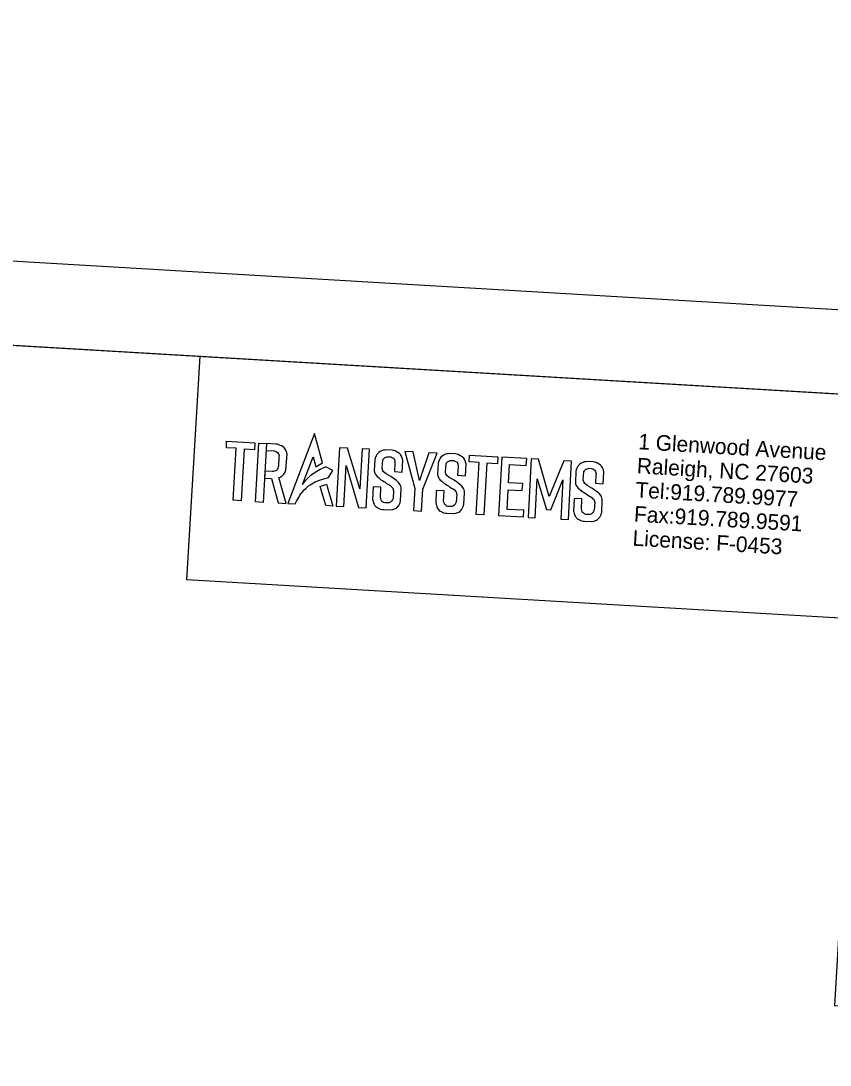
# Model space of a CAD drawing. Extents: x 2011701 to 2013463, y 444552 to 445750.
# Drawn here: x 2012984 to 2013225, y 445439.1 to 445750.4 of the extents above; entities that cross this region are included whole.
import ezdxf

# ---------------------------------------------------------------- set-up
doc = ezdxf.new("R2010")
doc.units = 0
for name, color, linetype in [('Old_Level_1', 7, 'Continuous'), ('Old_Level_2', 7, 'Continuous'), ('Old_Level_58', 7, 'Continuous'), ('Sheet Clip Boundary CELL', 7, 'Continuous'), ('Sheet Plan And Profile CELL', 7, 'Continuous'), ('Sheet Plot Border Outside CELL', 7, 'Continuous')]:
    doc.layers.add(name, color=color, linetype=linetype)

msp = doc.modelspace()

# ---------------------------------------------------------------- linework, layer by layer
at = {"layer": 'Old_Level_1'}
for points in [[(2013045.24, 445625.13), (2013053.69, 445624.64), (2013053.57, 445622.56), (2013050.46, 445622.74), (2013049.57, 445607.35), (2013047.22, 445607.48), (2013048.12, 445622.98), (2013045.16, 445623.16)], [(2013071.38, 445627.44), (2013063.47, 445606.53), (2013065.69, 445606.41), (2013066.08, 445607.23), (2013066.72, 445608.36), (2013067.07, 445608.97), (2013067.47, 445609.48), (2013068.04, 445610.21), (2013068.4, 445610.66), (2013068.8, 445611.02), (2013069.2, 445611.39), (2013069.72, 445611.86), (2013070.14, 445612.11), (2013070.58, 445612.41), (2013071.15, 445612.7), (2013071.66, 445612.95), (2013072.91, 445613.45), (2013073.93, 445613.8), (2013075.6, 445614.26), (2013076.86, 445616.33), (2013074.75, 445617.42), (2013073.07, 445616.63), (2013071.64, 445615.8), (2013070.61, 445615.07), (2013070.06, 445614.67), (2013069.5, 445614.14), (2013068.93, 445613.6), (2013068.51, 445613.2), (2013068.09, 445612.58), (2013067.86, 445612.23), (2013070.98, 445620.44), (2013071.81, 445617.5), (2013073.78, 445618.64)], [(2013054.84, 445624.55), (2013057.15, 445624.42), (2013056.13, 445606.88), (2013053.82, 445607.02)], [(2013057.03, 445622.34), (2013059.41, 445622.2), (2013059.71, 445622.13), (2013060.1, 445621.95), (2013060.42, 445621.71), (2013060.63, 445621.42), (2013060.77, 445621.09), (2013060.87, 445620.82), (2013060.84, 445620.24), (2013060.7, 445617.75), (2013060.62, 445617.43), (2013060.51, 445616.99), (2013060.36, 445616.71), (2013060.15, 445616.46), (2013059.87, 445616.26), (2013059.43, 445616.13), (2013059.11, 445616.11), (2013058.78, 445616.09), (2013056.67, 445616.2), (2013056.56, 445614.1), (2013058.66, 445613.98), (2013060.61, 445606.69), (2013063.02, 445606.58), (2013060.82, 445614.26), (2013061.21, 445614.37), (2013061.77, 445614.74), (2013062.28, 445615.24), (2013062.67, 445615.85), (2013062.92, 445616.47), (2013062.92, 445616.66), (2013063.23, 445621.22), (2013063.07, 445621.97), (2013062.75, 445622.67), (2013062.36, 445623.17), (2013061.69, 445623.68), (2013061.03, 445623.94), (2013060.37, 445624.21), (2013059.96, 445624.23), (2013057.15, 445624.42)], [(2013078.91, 445623.17), (2013077.9, 445605.74), (2013080.13, 445605.61), (2013080.84, 445617.87), (2013084.56, 445605.33), (2013086.81, 445605.22), (2013087.82, 445622.7), (2013085.65, 445622.82), (2013084.96, 445610.86), (2013081.26, 445623.04)], [(2013095.22, 445616.03), (2013097.52, 445615.9), (2013097.72, 445619.37), (2013097.57, 445620.08), (2013097.33, 445620.69), (2013097.05, 445621.09), (2013096.7, 445621.47), (2013096.28, 445621.78), (2013095.86, 445621.97), (2013095.86, 445621.97), (2013095.42, 445622.19), (2013094.94, 445622.34), (2013094.63, 445622.44), (2013092.88, 445622.51), (2013092.35, 445622.45), (2013091.89, 445622.4), (2013091.41, 445622.19), (2013091, 445622), (2013090.58, 445621.74), (2013090.26, 445621.44), (2013089.99, 445621.09), (2013089.78, 445620.71), (2013089.48, 445620.03), (2013089.4, 445619.52), (2013089.21, 445616.36), (2013089.3, 445615.87), (2013089.5, 445615.37), (2013089.76, 445614.94), (2013090.04, 445614.61), (2013090.47, 445614.24), (2013090.9, 445613.87), (2013091.17, 445613.63), (2013091.64, 445613.38), (2013092.11, 445613.12), (2013092.49, 445612.85), (2013092.91, 445612.54), (2013093.42, 445612.24), (2013093.84, 445611.99), (2013094.25, 445611.65), (2013094.54, 445611.34), (2013094.78, 445611.09), (2013094.9, 445610.6), (2013094.98, 445610.3), (2013094.81, 445608.07), (2013094.62, 445607.59), (2013094.36, 445607.19), (2013094.01, 445606.92), (2013093.65, 445606.78), (2013093.3, 445606.73), (2013092.34, 445606.76), (2013092.02, 445606.87), (2013091.71, 445607.08), (2013091.39, 445607.3), (2013091.27, 445607.64), (2013091.15, 445607.98), (2013091.05, 445608.25), (2013091.2, 445611.36), (2013088.86, 445611.47), (2013088.68, 445607.77), (2013088.79, 445607.48), (2013089.01, 445606.6), (2013089.16, 445606.3), (2013089.4, 445605.97), (2013089.75, 445605.57), (2013090.05, 445605.36), (2013090.47, 445605.15), (2013090.62, 445605.08), (2013091.04, 445604.87), (2013091.57, 445604.79), (2013091.96, 445604.72), (2013094.1, 445604.65), (2013094.71, 445604.76), (2013095.55, 445605.08), (2013095.84, 445605.19), (2013096.51, 445605.95), (2013096.89, 445606.71), (2013097.08, 445607.41), (2013097.23, 445610.83), (2013097.25, 445611.3), (2013097.14, 445611.69), (2013096.97, 445612.05), (2013096.48, 445612.84), (2013095.8, 445613.44), (2013094.86, 445614.07), (2013094.15, 445614.56), (2013092.73, 445615.41), (2013092.01, 445616.02), (2013091.71, 445616.46), (2013091.65, 445616.74), (2013091.59, 445617.03), (2013091.78, 445619.46), (2013091.91, 445619.7), (2013092.05, 445619.95), (2013092.24, 445620.09), (2013092.48, 445620.27), (2013092.75, 445620.37), (2013093.01, 445620.46), (2013093.16, 445620.42), (2013093.18, 445620.49), (2013094.13, 445620.42), (2013094.4, 445620.3), (2013094.67, 445620.17), (2013094.94, 445620.05), (2013095.06, 445619.84), (2013095.23, 445619.56), (2013095.31, 445619.27), (2013095.38, 445618.99), (2013095.36, 445618.69)], [(2013100.84, 445621.89), (2013098.31, 445622.04), (2013101.28, 445610.96), (2013100.93, 445604.43), (2013103.31, 445604.3), (2013103.66, 445610.78), (2013107.96, 445621.51), (2013105.47, 445621.59), (2013102.67, 445613.4)], [(2013114.06, 445614.94), (2013116.36, 445614.8), (2013116.57, 445618.27), (2013116.41, 445618.99), (2013116.17, 445619.59), (2013115.89, 445620), (2013115.54, 445620.37), (2013115.12, 445620.68), (2013114.71, 445620.88), (2013114.71, 445620.88), (2013114.26, 445621.1), (2013113.78, 445621.25), (2013113.47, 445621.35), (2013111.72, 445621.42), (2013111.19, 445621.36), (2013110.73, 445621.31), (2013110.25, 445621.09), (2013109.84, 445620.91), (2013109.43, 445620.65), (2013109.1, 445620.35), (2013108.83, 445620), (2013108.62, 445619.62), (2013108.32, 445618.94), (2013108.24, 445618.43), (2013108.06, 445615.26), (2013108.14, 445614.78), (2013108.34, 445614.27), (2013108.6, 445613.85), (2013108.88, 445613.52), (2013109.31, 445613.15), (2013109.74, 445612.77), (2013110.01, 445612.54), (2013110.48, 445612.28), (2013110.95, 445612.03), (2013111.33, 445611.76), (2013111.75, 445611.44), (2013112.26, 445611.15), (2013112.68, 445610.9), (2013113.09, 445610.56), (2013113.38, 445610.25), (2013113.62, 445610), (2013113.74, 445609.51), (2013113.82, 445609.2), (2013113.65, 445606.97), (2013113.46, 445606.5), (2013113.2, 445606.1), (2013112.85, 445605.82), (2013112.49, 445605.68), (2013112.14, 445605.63), (2013111.18, 445605.67), (2013110.87, 445605.78), (2013110.55, 445605.99), (2013110.23, 445606.2), (2013110.11, 445606.55), (2013109.99, 445606.89), (2013109.89, 445607.16), (2013110.04, 445610.27), (2013107.7, 445610.38), (2013107.53, 445606.68), (2013107.63, 445606.39), (2013107.85, 445605.51), (2013108, 445605.21), (2013108.24, 445604.88), (2013108.59, 445604.48), (2013108.89, 445604.27), (2013109.31, 445604.06), (2013109.46, 445603.98), (2013109.88, 445603.78), (2013110.41, 445603.69), (2013110.8, 445603.63), (2013112.94, 445603.56), (2013113.55, 445603.67), (2013114.39, 445603.99), (2013114.68, 445604.1), (2013115.35, 445604.85), (2013115.73, 445605.62), (2013115.92, 445606.32), (2013116.07, 445609.74), (2013116.09, 445610.21), (2013115.98, 445610.59), (2013115.81, 445610.96), (2013115.32, 445611.75), (2013114.64, 445612.34), (2013113.71, 445612.98), (2013112.99, 445613.47), (2013111.57, 445614.32), (2013110.85, 445614.92), (2013110.55, 445615.36), (2013110.49, 445615.65), (2013110.43, 445615.94), (2013110.62, 445618.36), (2013110.76, 445618.61), (2013110.89, 445618.86), (2013111.08, 445619), (2013111.32, 445619.18), (2013111.59, 445619.27), (2013111.85, 445619.37), (2013112, 445619.33), (2013112.02, 445619.4), (2013112.97, 445619.33), (2013113.24, 445619.2), (2013113.51, 445619.08), (2013113.79, 445618.95), (2013113.9, 445618.75), (2013114.07, 445618.46), (2013114.15, 445618.18), (2013114.22, 445617.9), (2013114.2, 445617.6)], [(2013117.57, 445620.93), (2013126.03, 445620.44), (2013125.91, 445618.37), (2013122.8, 445618.55), (2013121.91, 445603.15), (2013119.56, 445603.29), (2013120.46, 445618.79), (2013117.49, 445618.96)], [(2013134.62, 445619.93), (2013127.24, 445620.36), (2013126.23, 445602.96), (2013133.69, 445602.53), (2013133.81, 445604.5), (2013128.77, 445604.79), (2013129.11, 445610.62), (2013133.32, 445610.38), (2013133.44, 445612.45), (2013129.19, 445612.69), (2013129.51, 445618.18), (2013134.52, 445617.89)], [(2013141.34, 445608.67), (2013138.18, 445619.79), (2013135.96, 445619.82), (2013135.02, 445602.38), (2013137.13, 445602.27), (2013137.76, 445613.93), (2013140.49, 445604.77), (2013141.83, 445604.65), (2013145.43, 445613.59), (2013144.79, 445601.88), (2013147.07, 445601.76), (2013148.02, 445619.15), (2013145.73, 445619.28)], [(2013155.12, 445612.55), (2013157.43, 445612.42), (2013157.63, 445615.89), (2013157.47, 445616.61), (2013157.23, 445617.21), (2013156.95, 445617.62), (2013156.6, 445617.99), (2013156.18, 445618.3), (2013155.77, 445618.5), (2013155.77, 445618.5), (2013155.32, 445618.72), (2013154.85, 445618.87), (2013154.53, 445618.97), (2013152.78, 445619.03), (2013152.25, 445618.97), (2013151.79, 445618.92), (2013151.32, 445618.71), (2013150.9, 445618.52), (2013150.49, 445618.26), (2013150.16, 445617.97), (2013149.9, 445617.62), (2013149.68, 445617.24), (2013149.38, 445616.56), (2013149.3, 445616.04), (2013149.12, 445612.88), (2013149.2, 445612.4), (2013149.4, 445611.89), (2013149.67, 445611.46), (2013149.95, 445611.14), (2013150.38, 445610.76), (2013150.81, 445610.39), (2013151.08, 445610.15), (2013151.55, 445609.9), (2013152.02, 445609.65), (2013152.39, 445609.37), (2013152.81, 445609.06), (2013153.33, 445608.76), (2013153.74, 445608.52), (2013154.16, 445608.18), (2013154.45, 445607.87), (2013154.68, 445607.61), (2013154.81, 445607.13), (2013154.88, 445606.82), (2013154.72, 445604.59), (2013154.53, 445604.12), (2013154.26, 445603.71), (2013153.91, 445603.44), (2013153.55, 445603.3), (2013153.21, 445603.25), (2013152.25, 445603.29), (2013151.93, 445603.4), (2013151.61, 445603.61), (2013151.29, 445603.82), (2013151.17, 445604.16), (2013151.05, 445604.51), (2013150.95, 445604.78), (2013151.1, 445607.89), (2013148.76, 445608), (2013148.59, 445604.29), (2013148.69, 445604), (2013148.91, 445603.13), (2013149.07, 445602.83), (2013149.3, 445602.49), (2013149.66, 445602.1), (2013149.95, 445601.89), (2013150.37, 445601.68), (2013150.53, 445601.6), (2013150.95, 445601.4), (2013151.48, 445601.31), (2013151.87, 445601.25), (2013154.01, 445601.18), (2013154.61, 445601.28), (2013155.46, 445601.61), (2013155.74, 445601.72), (2013156.41, 445602.47), (2013156.79, 445603.24), (2013156.99, 445603.94), (2013157.13, 445607.36), (2013157.15, 445607.83), (2013157.05, 445608.21), (2013156.87, 445608.58), (2013156.38, 445609.36), (2013155.71, 445609.96), (2013154.77, 445610.6), (2013154.05, 445611.08), (2013152.64, 445611.94), (2013151.92, 445612.54), (2013151.61, 445612.98), (2013151.55, 445613.27), (2013151.49, 445613.56), (2013151.68, 445615.98), (2013151.82, 445616.23), (2013151.96, 445616.48), (2013152.14, 445616.62), (2013152.39, 445616.8), (2013152.65, 445616.89), (2013152.92, 445616.98), (2013153.06, 445616.95), (2013153.08, 445617.02), (2013154.04, 445616.95), (2013154.31, 445616.82), (2013154.58, 445616.7), (2013154.85, 445616.57), (2013154.97, 445616.37), (2013155.14, 445616.08), (2013155.21, 445615.8), (2013155.29, 445615.52), (2013155.26, 445615.21)], [(2013073.06, 445611.61), (2013075.02, 445612.26), (2013076.9, 445605.7), (2013074.81, 445605.9)]]:
    msp.add_lwpolyline(points, close=True, dxfattribs=at)
at = {"layer": 'Old_Level_58'}
msp.add_lwpolyline([(2013037.32, 445650.4), (2013237.02, 445638.63), (2013233.1, 445572.05), (2013033.4, 445583.82)], close=True, dxfattribs=at)
at = {"layer": 'Sheet Clip Boundary CELL'}
msp.add_lwpolyline([(2011939.33, 445715.12), (2013237.02, 445638.63), (2013226.31, 445456.93), (2013426.02, 445445.16), (2013374.94, 444578.67), (2011877.54, 444666.94)], close=True, dxfattribs=at)
at = {"layer": 'Sheet Plan And Profile CELL'}
msp.add_lwpolyline([(2013436.73, 445626.85), (2011939.33, 445715.12), (2011877.54, 444666.94), (2013374.94, 444578.67)], close=True, dxfattribs=at)
at = {"layer": 'Sheet Plot Border Outside CELL'}
msp.add_lwpolyline([(2011701.37, 444652.28), (2013398.42, 444552.25), (2013463.16, 445650.34), (2011766.1, 445750.38)], close=True, dxfattribs=at)

# ---------------------------------------------------------------- texts
at = {"layer": 'Old_Level_2'}
for s, p in [('1 Glenwood Avenue', (2013167.77, 445622.71)), ('Raleigh, NC 27603', (2013167.34, 445615.53)), ('Tel:919.789.9977 ', (2013166.92, 445608.34)), ('Fax:919.789.9591', (2013166.49, 445601.16)), ('License: F-0453', (2013166.07, 445593.98))]:
    msp.add_text(s, height=4.6576, rotation=356.6264, dxfattribs=at).set_placement(p)

doc.saveas('drawing.dxf')
